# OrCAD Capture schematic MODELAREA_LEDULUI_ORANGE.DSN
size A
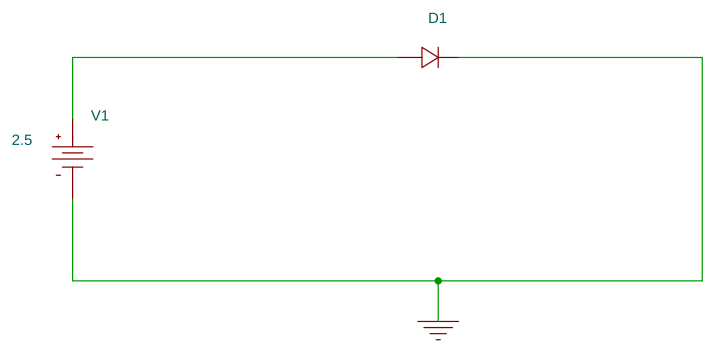
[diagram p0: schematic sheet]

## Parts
D1  Dbreak
V1  VDC

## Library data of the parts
D1 = Dbreak
V1 = VDC: DC: 2.5

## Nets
0: D1.1(2) V1.1(-)
N00067: D1.0(1) V1.0(+)
